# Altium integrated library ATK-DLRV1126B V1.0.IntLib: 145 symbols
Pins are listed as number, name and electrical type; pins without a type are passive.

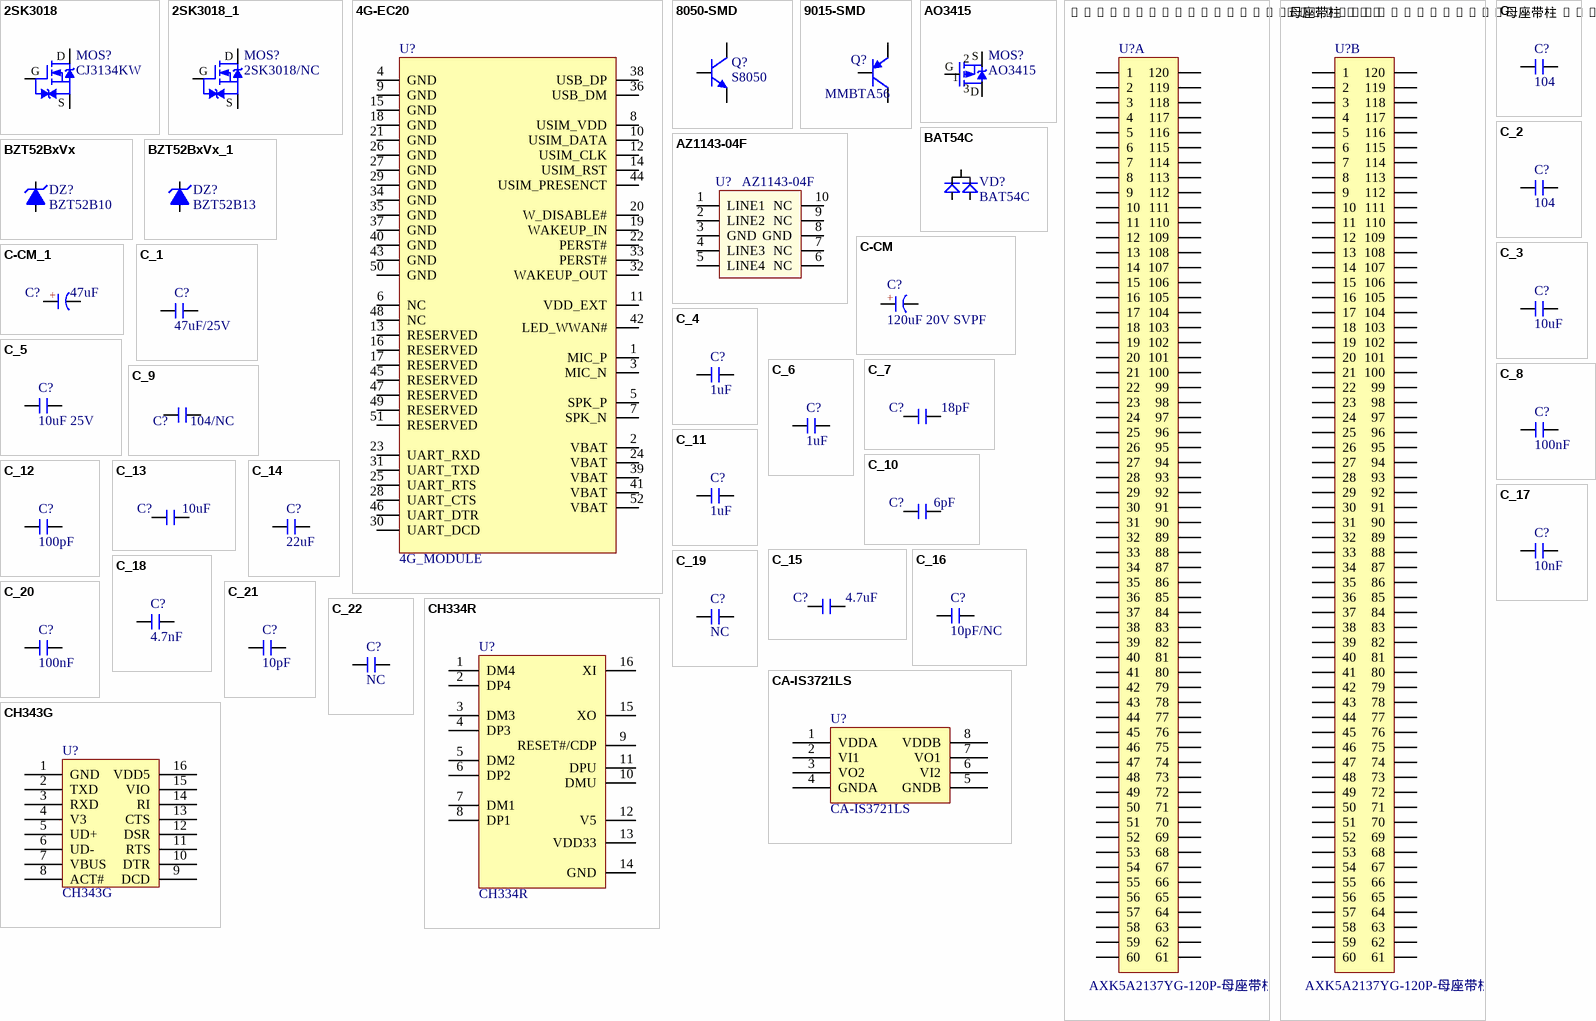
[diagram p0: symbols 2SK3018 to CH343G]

## 2SK3018
designator MOS?, comment CJ3134KW
NMOS  30V 0.1A@2.5V 8Ω; BOM名称: N沟场效应管; 版权归属: 正点原子; Parameter: MOS管
footprint SOT323-3L (2x2.2x0.9mm(长宽高))
footprint SOT323-3M (2x2.2x0.9mm(长宽高))
footprint SOT323-3N (2x2.2x0.9mm(长宽高))
footprint SOT23-3L (3x1.3x1mm(长宽高))
footprint SOT23-3N (3x1.3x1mm(长宽高))
footprint SOT23-3M (3x1.3x1mm(长宽高))
footprint SOT323-3L (2x2.2x0.9mm(长宽高))
pins: 1 G, 2 S, 3 D

## 2SK3018_1
designator MOS?, comment 2SK3018/NC
NMOS  30V 0.1A@2.5V 8Ω; BOM名称: N沟场效应管; 版权归属: 正点原子; Parameter: MOS管
footprint SOT323-3L (2x2.2x0.9mm(长宽高))
footprint SOT323-3M (2x2.2x0.9mm(长宽高))
footprint SOT323-3N (2x2.2x0.9mm(长宽高))
footprint SOT23-3L (3x1.3x1mm(长宽高))
footprint SOT23-3N (3x1.3x1mm(长宽高))
footprint SOT23-3M (3x1.3x1mm(长宽高))
footprint SOT323-3L (2x2.2x0.9mm(长宽高))
pins: 1 G, 2 S, 3 D

## 4G-EC20
designator U?, comment 4G_MODULE
footprint Mini PCIE 52P
pins: 1 MIC_P, 2 VBAT, 3 MIC_N, 4 GND, 5 SPK_P, 6 NC, 7 SPK_N, 8 USIM_VDD, 9 GND, 10 USIM_DATA, 11 VDD_EXT, 12 USIM_CLK, 13 RESERVED, 14 USIM_RST, 15 GND, 16 RESERVED, 17 RESERVED, 18 GND, 19 WAKEUP_IN, 20 W_DISABLE#, 21 GND, 22 PERST#, 23 UART_RXD, 24 VBAT, 25 UART_RTS, 26 GND, 27 GND, 28 UART_CTS, 29 GND, 30 UART_DCD, 31 UART_TXD, 32 WAKEUP_OUT, 33 PERST#, 34 GND, 35 GND, 36 USB_DM, 37 GND, 38 USB_DP, 39 VBAT, 40 GND, 41 VBAT, 42 LED_WWAN#, 43 GND, 44 USIM_PRESENCT, 45 RESERVED, 46 UART_DTR, 47 RESERVED, 48 NC, 49 RESERVED, 50 GND, 51 RESERVED, 52 VBAT

## 8050-SMD
designator Q?, comment S8050
高频放大-NPN型; 版权归属: 正点原子; 属性: 40V 1.5A 1W 100MHZ; Parameter: 三极管
footprint SOT23-3N (3x1.3x1mm(长宽高))
footprint SOT23-3L (3x1.3x1mm(长宽高))
footprint SOT23-3M (3x1.3x1mm(长宽高))
footprint SOT323-3L (2x2.2x0.9mm(长宽高))
footprint SOT323-3N (2x2.2x0.9mm(长宽高))
footprint SOT323-3M (2x2.2x0.9mm(长宽高))
pins: 1 B, 2 E, 3 C

## 9015-SMD
designator Q?, comment MMBTA56
低噪放大-PNP型; BOM名称: 三极管; 版权归属: 正点原子; 属性: 50V 0.1A 0.4W 150MHZ
footprint SOT23-3N (3x1.3x1mm(长宽高))
footprint SOT23-3L (3x1.3x1mm(长宽高))
footprint SOT23-3M (3x1.3x1mm(长宽高))
pins: 1 B, 2 E, 3 C

## AO3415
designator MOS?
PMOS -20V-4.3A 45mΩ; BOM名称: P沟道场效应管; 版权归属: 正点原子; Parameter: MOS管
footprint SOT23-3N (3x1.3x1mm(长宽高))
footprint SOT23-3L (3x1.3x1mm(长宽高))
footprint SOT23-3M (3x1.3x1mm(长宽高))
pins: 1 G, 2 S, 3 D

## AXK5A2137YG-120P-母座带柱
designator U?
footprint ATK-CLRV1126B-CORE (公座)
part A pins: A1 1, A2 2, A3 3, A4 4, A5 5, A6 6, A7 7, A8 8, A9 9, A10 10, A11 11, A12 12, A13 13, A14 14, A15 15, A16 16, A17 17, A18 18, A19 19, A20 20, A21 21, A22 22, A23 23, A24 24, A25 25, A26 26, A27 27, A28 28, A29 29, A30 30, A31 31, A32 32, A33 33, A34 34, A35 35, A36 36, A37 37, A38 38, A39 39, A40 40, A41 41, A42 42, A43 43, A44 44, A45 45, A46 46, A47 47, A48 48, A49 49, A50 50, A51 51, A52 52, A53 53, A54 54, A55 55, A56 56, A57 57, A58 58, A59 59, A60 60, A61 61, A62 62, A63 63, A64 64, A65 65, A66 66, A67 67, A68 68, A69 69, A70 70, A71 71, A72 72, A73 73, A74 74, A75 75, A76 76, A77 77, A78 78, A79 79, A80 80, A81 81, A82 82, A83 83, A84 84, A85 85, A86 86, A87 87, A88 88, A89 89, A90 90, A91 91, A92 92, A93 93, A94 94, A95 95, A96 96, A97 97, A98 98, A99 99, A100 100, A101 101, A102 102, A103 103, A104 104, A105 105, A106 106, A107 107, A108 108, A109 109, A110 110, A111 111, A112 112, A113 113, A114 114, A115 115, A116 116, A117 117, A118 118, A119 119, A120 120
part B pins: B1 1, B2 2, B3 3, B4 4, B5 5, B6 6, B7 7, B8 8, B9 9, B10 10, B11 11, B12 12, B13 13, B14 14, B15 15, B16 16, B17 17, B18 18, B19 19, B20 20, B21 21, B22 22, B23 23, B24 24, B25 25, B26 26, B27 27, B28 28, B29 29, B30 30, B31 31, B32 32, B33 33, B34 34, B35 35, B36 36, B37 37, B38 38, B39 39, B40 40, B41 41, B42 42, B43 43, B44 44, B45 45, B46 46, B47 47, B48 48, B49 49, B50 50, B51 51, B52 52, B53 53, B54 54, B55 55, B56 56, B57 57, B58 58, B59 59, B60 60, B61 61, B62 62, B63 63, B64 64, B65 65, B66 66, B67 67, B68 68, B69 69, B70 70, B71 71, B72 72, B73 73, B74 74, B75 75, B76 76, B77 77, B78 78, B79 79, B80 80, B81 81, B82 82, B83 83, B84 84, B85 85, B86 86, B87 87, B88 88, B89 89, B90 90, B91 91, B92 92, B93 93, B94 94, B95 95, B96 96, B97 97, B98 98, B99 99, B100 100, B101 101, B102 102, B103 103, B104 104, B105 105, B106 106, B107 107, B108 108, B109 109, B110 110, B111 111, B112 112, B113 113, B114 114, B115 115, B116 116, B117 117, B118 118, B119 119, B120 120

## AZ1143-04F
designator U?
ESD保护二极管阵列
footprint DFN2510P10E
pins: 1 LINE1, 2 LINE2, 3 GND, 4 LINE3, 5 LINE4, 6 NC, 7 NC, 8 GND, 9 NC, 10 NC

## BAT54C
designator VD?
肖特基二极管（双）
footprint SOT23-3N (3x1.3x1mm(长宽高))
footprint SOT23-3L (3x1.3x1mm(长宽高))
footprint SOT23-3M (3x1.3x1mm(长宽高))
pins: 1, 2, 3

## BZT52BxVx
designator DZ?, comment BZT52B10
CJ x.xV / 0.5W稳压管  2%; 版权归属: 正点原子; BOM名称: 二极管(稳压)
footprint SOD-123 (2.7x1.6X1.1mm（长宽高，不包括引脚）)
footprint SMB (二极管 SMB)
footprint SOD-123 (二极管)
pins: 1 A, 2 K

## BZT52BxVx_1
designator DZ?, comment BZT52B13
CJ x.xV / 0.5W稳压管  2%; 版权归属: 正点原子; BOM名称: 二极管(稳压)
footprint SOD-123 (2.7x1.6X1.1mm（长宽高，不包括引脚）)
footprint Model Name (Model Description)
footprint Model Name (Model Description)
footprint SMB (二极管 SMB)
footprint SOD-123 (二极管)
pins: 1 A, 2 K

## C
designator C?, comment 104
无极性贴片电容; 版权归属: 源创客
footprint C 0402 (无极性贴片电容)
pins: 1, 2

## C-CM
designator C?, comment 120uF 20V SVPF
贴片电解电容; 版权归属: 源创客
footprint CM A(3*5.4) (贴片电解电容，直径3mm，高5.4mm)
footprint CM B(4*5.4) (贴片电解电容，直径4mm，高5.4mm)
footprint CM C(5*5.4) (贴片电解电容，直径5mm，高5.4mm)
footprint CM D(6.3*5.4) (贴片电解电容，直径6.3mm，高5.4mm)
footprint CM D(6.3*7.7) (贴片电解电容，直径6.3mm，高7.7mm)
footprint CM E(8*6.2) (贴片电解电容，直径8mm，高6.2mm)
footprint CM E(8*10.2) (贴片电解电容，直径8mm，高10.2mm)
footprint CM F(10*10.2) (贴片电解电容，直径10mm，高10.2mm)
footprint CM G(12.5*13.5) (贴片电解电容，直径12.5mm，高13.5mm)
footprint CM G(12.5*16) (贴片电解电容，直径12.5mm，高16mm)
footprint CM H(16*16.5) (贴片电解电容，直径16mm，高16.5mm)
pins: 1 A, 2 K

## C-CM_1
designator C?, comment 47uF
贴片电解电容; 版权归属: 源创客
footprint CM A(3*5.4) (贴片电解电容，直径3mm，高5.4mm)
footprint CM B(4*5.4) (贴片电解电容，直径4mm，高5.4mm)
footprint CM C(5*5.4) (贴片电解电容，直径5mm，高5.4mm)
footprint CM D(6.3*5.4) (贴片电解电容，直径6.3mm，高5.4mm)
footprint CM D(6.3*7.7) (贴片电解电容，直径6.3mm，高7.7mm)
footprint CM E(8*6.2) (贴片电解电容，直径8mm，高6.2mm)
footprint CM E(8*10.2) (贴片电解电容，直径8mm，高10.2mm)
footprint CM F(10*10.2) (贴片电解电容，直径10mm，高10.2mm)
footprint CM G(12.5*13.5) (贴片电解电容，直径12.5mm，高13.5mm)
footprint CM G(12.5*16) (贴片电解电容，直径12.5mm，高16mm)
footprint CM H(16*16.5) (贴片电解电容，直径16mm，高16.5mm)
pins: 1 A, 2 K

## C_1
designator C?, comment 47uF/25V
无极性贴片电容; 版权归属: 源创客
footprint C 0201 (无极性贴片电容)
footprint C 0402 (无极性贴片电容)
footprint C 0603 (无极性贴片电容)
footprint C 0805 (无极性贴片电容)
footprint C 1206 (无极性贴片电容)
footprint C 1210 (无极性贴片电容)
footprint C 1808 (无极性贴片电容)
footprint C 1812 (无极性贴片电容)
footprint C 1825 (无极性贴片电容)
footprint C 2225 (无极性贴片电容)
pins: 1, 2

## C_2
designator C?, comment 104
无极性贴片电容; 版权归属: 源创客
footprint C 0402 (无极性贴片电容)
pins: 1, 2

## C_3
designator C?, comment 10uF
无极性贴片电容; 版权归属: 源创客
footprint C 0201 (无极性贴片电容)
footprint C 0402 (无极性贴片电容)
footprint C 0603 (无极性贴片电容)
footprint C 0805 (无极性贴片电容)
footprint C 1206 (无极性贴片电容)
footprint C 1210 (无极性贴片电容)
footprint C 1808 (无极性贴片电容)
footprint C 1812 (无极性贴片电容)
footprint C 1825 (无极性贴片电容)
footprint C 2225 (无极性贴片电容)
footprint C 0603 (无极性贴片电容(0603))
pins: 1, 2

## C_4
designator C?, comment 1uF
50V 10% 无极性贴片电容; BOM名称: 电容; 版权归属: 正点原子
footprint C 0201 (无极性贴片电容)
footprint C 0402 (无极性贴片电容)
footprint C 0603 (无极性贴片电容)
footprint C 0805 (无极性贴片电容)
footprint C 1206 (无极性贴片电容)
footprint C 1210 (无极性贴片电容)
footprint C 1808 (无极性贴片电容)
footprint C 1812 (无极性贴片电容)
footprint C 1825 (无极性贴片电容)
footprint C 2225 (无极性贴片电容)
footprint C 0805 (无极性贴片电容(0805))
footprint C 0603 (无极性贴片电容(0603))
pins: 1, 2

## C_5
designator C?, comment 10uF 25V
无极性贴片电容; 版权归属: 源创客
footprint C 0201 (无极性贴片电容)
footprint C 0402 (无极性贴片电容)
footprint C 0603 (无极性贴片电容)
footprint C 0805 (无极性贴片电容)
footprint C 1206 (无极性贴片电容)
footprint C 1210 (无极性贴片电容)
footprint C 1808 (无极性贴片电容)
footprint C 1812 (无极性贴片电容)
footprint C 1825 (无极性贴片电容)
footprint C 2225 (无极性贴片电容)
pins: 1, 2

## C_6
designator C?, comment 1uF
无极性贴片电容; 版权归属: 源创客
footprint C 0402 (无极性贴片电容)
pins: 1, 2

## C_7
designator C?, comment 18pF
无极性贴片电容; 版权归属: 源创客
footprint C 0402 (无极性贴片电容)
pins: 1, 2

## C_8
designator C?, comment 100nF
无极性电容; BOM名称: 无极性贴片电容; 版权归属: 正点原子
footprint C 0402 (无极性贴片电容(0402))
pins: 1, 2

## C_9
designator C?, comment 104/NC
无极性贴片电容; 版权归属: 正点原子
footprint C 0402 (无极性贴片电容)
pins: 1, 2

## C_10
designator C?, comment 6pF
无极性贴片电容; 版权归属: 正点原子
footprint C 0402 (无极性贴片电容)
pins: 1, 2

## C_11
designator C?, comment 1uF
无极性贴片电容; 版权归属: 正点原子
footprint C 0402 (无极性贴片电容)
pins: 1, 2

## C_12
designator C?, comment 100pF
无极性贴片电容; 版权归属: 正点原子
footprint C 0402 (无极性贴片电容)
pins: 1, 2

## C_13
designator C?, comment 10uF
无极性贴片电容; 版权归属: 正点原子
footprint C 0201 (无极性贴片电容)
footprint C 0402 (无极性贴片电容)
footprint C 0603 (无极性贴片电容)
footprint C 0805 (无极性贴片电容)
footprint C 1206 (无极性贴片电容)
footprint C 1210 (无极性贴片电容)
footprint C 1808 (无极性贴片电容)
footprint C 1812 (无极性贴片电容)
footprint C 1825 (无极性贴片电容)
footprint C 2225 (无极性贴片电容)
pins: 1, 2

## C_14
designator C?, comment 22uF
无极性贴片电容; 版权归属: 正点原子
footprint C 0201 (无极性贴片电容)
footprint C 0402 (无极性贴片电容)
footprint C 0603 (无极性贴片电容)
footprint C 0805 (无极性贴片电容)
footprint C 1206 (无极性贴片电容)
footprint C 1210 (无极性贴片电容)
footprint C 1808 (无极性贴片电容)
footprint C 1812 (无极性贴片电容)
footprint C 1825 (无极性贴片电容)
footprint C 2225 (无极性贴片电容)
pins: 1, 2

## C_15
designator C?, comment 4.7uF
无极性贴片电容; 版权归属: 正点原子
footprint C 0402 (无极性贴片电容)
pins: 1, 2

## C_16
designator C?, comment 10pF/NC
无极性贴片电容; 版权归属: 正点原子
footprint C 0402 (无极性贴片电容)
pins: 1, 2

## C_17
designator C?, comment 10nF
无极性贴片电容; 版权归属: 正点原子
footprint C 0402 (无极性贴片电容)
pins: 1, 2

## C_18
designator C?, comment 4.7nF
无极性贴片电容; 版权归属: 正点原子
footprint C 0402 (无极性贴片电容)
pins: 1, 2

## C_19
designator C?, comment NC
无极性贴片电容; 版权归属: 正点原子
footprint C 0402 (无极性贴片电容)
pins: 1, 2

## C_20
designator C?, comment 100nF
无极性贴片电容; 版权归属: 源创客
footprint C 0402 (无极性贴片电容(0402))
pins: 1, 2

## C_21
designator C?, comment 10pF
无极性贴片电容; 版权归属: 源创客
footprint C 0402 (无极性贴片电容)
pins: 1, 2

## C_22
designator C?, comment NC
无极性贴片电容; 版权归属: 源创客
footprint C 0201 (无极性贴片电容)
footprint C 0402 (无极性贴片电容)
footprint C 0603 (无极性贴片电容)
footprint C 0805 (无极性贴片电容)
footprint C 1206 (无极性贴片电容)
footprint C 1210 (无极性贴片电容)
footprint C 1808 (无极性贴片电容)
footprint C 1812 (无极性贴片电容)
footprint C 1825 (无极性贴片电容)
footprint C 2225 (无极性贴片电容)
pins: 1, 2

## CA-IS3721LS
designator U?
footprint SOIC-8 6.2*5.1 (SOIC-8 6.2*5.1mm)
pins: 1 VDDA, 2 VI1, 3 VO2, 4 GNDA, 5 GNDB, 6 VI2, 7 VO1, 8 VDDB

## CH334R
designator U?
footprint QSOP16 (TSOP, 16-Leads, Body 4.90x3.90mm, Pitch 0.64mm, IPC Low Density)
pins: 1 DM4, 2 DP4, 3 DM3, 4 DP3, 5 DM2, 6 DP2, 7 DM1, 8 DP1, 9 RESET#/CDP, 10 DMU, 11 DPU, 12 V5, 13 VDD33, 14 GND, 15 XO, 16 XI

## CH343G
designator U?
footprint SOP16_M (10.3*6.2*1.8mm（长宽高）)
pins: 1 GND, 2 TXD, 3 RXD, 4 V3, 5 UD+, 6 UD-, 7 VBUS, 8 ACT#, 9 DCD, 10 DTR, 11 RTS, 12 DSR, 13 CTS, 14 RI, 15 VIO, 16 VDD5

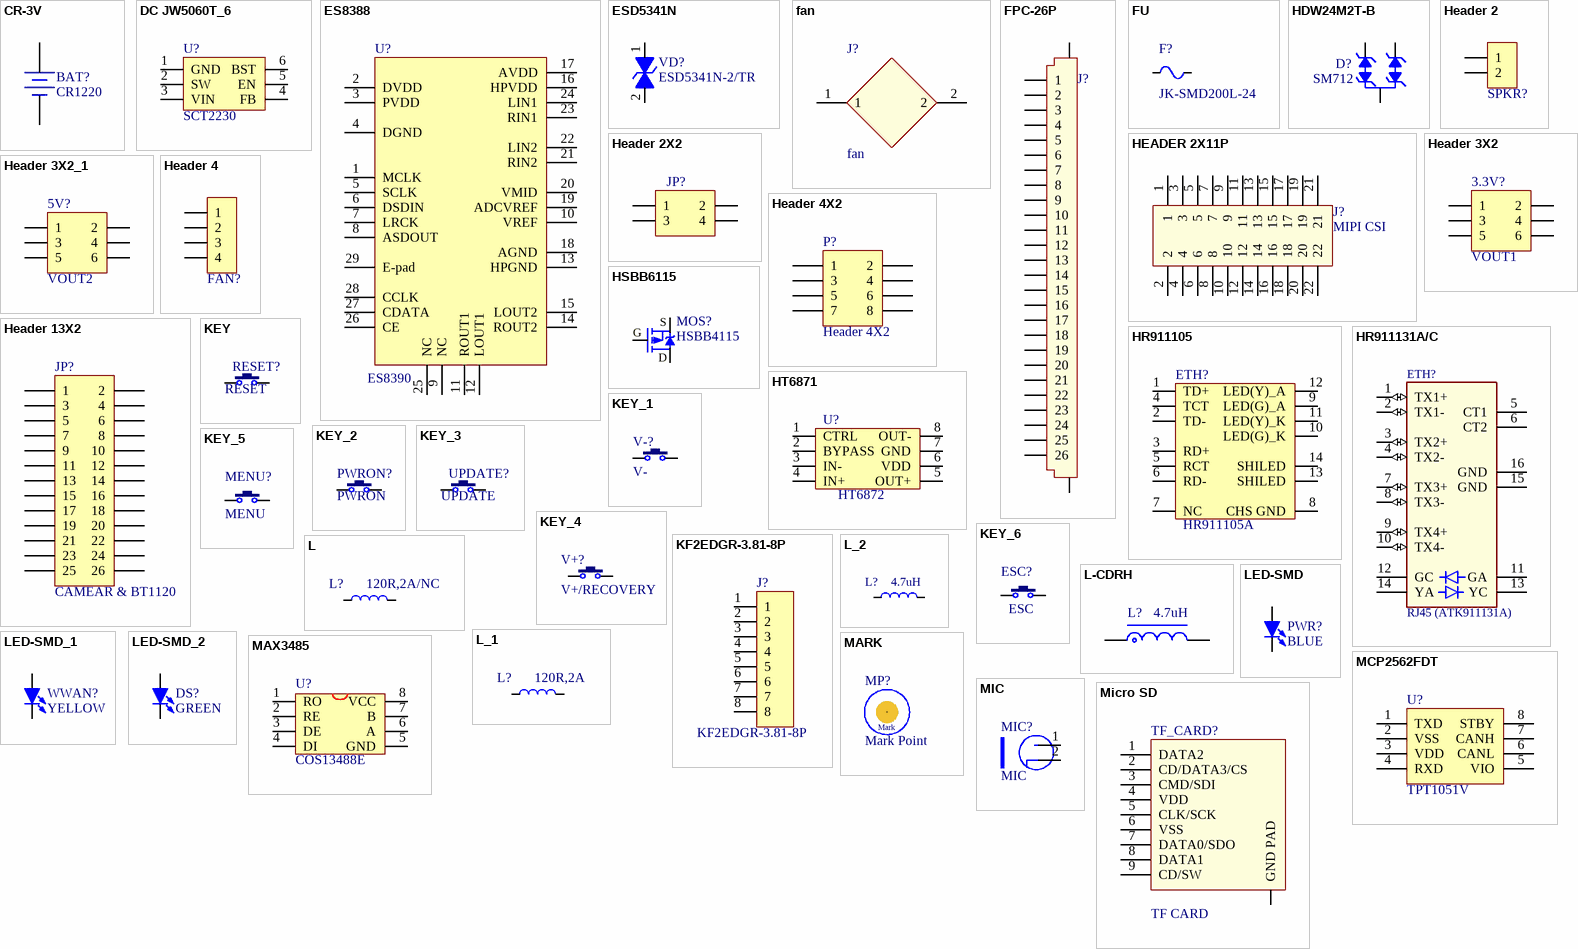
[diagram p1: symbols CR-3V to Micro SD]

## CR-3V
designator BAT?, comment CR1220
微型电池; 版权归属: 正点原子
footprint CR1220_A (纽扣电池座)
footprint CR1220_B (纽扣电池座)
footprint ML621FE (可充电纽扣电池)
footprint CR2032_A (纽扣电池座)
footprint CR2032_B (纽扣电池座)
pins: 1 DC+, 2 DC-

## DC JW5060T_6
designator U?, comment SCT2230
DC降压芯片
footprint SOT23-6L (3x1.6x1.1mm(长宽高))
footprint SOT23-6M (3x1.6x1.1mm(长宽高))
footprint SOT23-6N (3x1.6x1.1mm(长宽高))
pins: 1 GND, 2 SW, 3 VIN, 4 FB, 5 EN, 6 BST

## ES8388
designator U?, comment ES8390
footprint QFN28 4X4_L (QFN28P 长4mm，宽4mm)
pins: 1 MCLK, 2 DVDD, 3 PVDD, 4 DGND, 5 SCLK, 6 DSDIN, 7 LRCK, 8 ASDOUT, 9 NC, 10 VREF, 11 ROUT1, 12 LOUT1, 13 HPGND, 14 ROUT2, 15 LOUT2, 16 HPVDD, 17 AVDD, 18 AGND, 19 ADCVREF, 20 VMID, 21 RIN2, 22 LIN2, 23 RIN1, 24 LIN1, 25 NC, 26 CE, 27 CDATA, 28 CCLK, 29 E-pad

## ESD5341N
designator VD?, comment ESD5341N-2/TR
ESD二极管-单向
footprint ESD0402
pins: 1, 2

## fan
designator J?
footprint 40*40mm fan
footprint 40X40MM_FAN_59MM
pins: 1, 2

## FPC-26P
designator J?, comment FPC0.5-26P  (value not drawn)
FPC连接器; 版权归属: 正点原子; Parameter: 接口器件
footprint FPC 1.25 26P V-T (FPC插座1.25mm 26P 立式直插)
footprint FPC 1.0 26P H-S (FPC座1.0mm 26P 卧式贴片)
footprint FPC 0.5 26P H-S (FPC座 0.5mm 26P 卧式贴片)
footprint FPC 0.5 26P V-S (FPC座 0.5mm 26P 立式贴片)
footprint HEADER 2.0 2X11P (2.0mm 直插排针)
footprint FPC 0.5 26P V-S (FPC座 0.5mm 26P 立式贴片)
pins: 0, 0, 1, 2, 3, 4, 5, 6, 7, 8, 9, 10, 11, 12, 13, 14, 15, 16, 17, 18, 19, 20, 21, 22, 23, 24, 25, 26

## FU
designator F?, comment JK-SMD200L-24
贴片保险丝; 版权归属: 源创客
footprint FU 0402 (贴片保险丝)
footprint FU 0603 (贴片保险丝)
footprint FU 0805 (贴片保险丝)
footprint FU 1206 (贴片保险丝)
footprint FU 1210 (贴片保险丝)
footprint FU 1812 (贴片保险丝)
footprint FU 1812 (贴片保险丝)
pins: 1, 2

## HDW24M2T-B
designator D?, comment SM712
ESD
footprint SOT23-3L (3x1.3x1mm(长宽高))
pins: 1, 2, 3

## Header 2
designator SPKR?, comment SPKL  (value not drawn)
2P接插件; 版权归属: 源创客
footprint HDR-1X2 (排针，2脚)
footprint HDR-1X2_H (弯脚排针，2脚)
footprint HDR-1X2_M (排母，2脚)
footprint HDR-1X2_Y (圆孔排母，2脚)
footprint XH2.54-2P (接插件，2P)
footprint KF2510-2P (接插件/2A)
footprint VH3.96-2P (接插件，25V/5A)
footprint XH2.54-2P_H (接插件，2P)
footprint VH3.96-2P_H (接插件，25V/5A)
footprint KF301-2P (可拼接端子/6A)
footprint KF2EDGK5.0-2P (直列插拔式端子)
footprint PH2.0 D-L-2P (接插件/1A)
footprint PH2.0 D-W-2P (接插件/1A)
footprint KF2EDGK5.0-2P_H (弯角插拔式端子)
footprint KF7620-2P (15.2*12*12mm(长宽高))
footprint KF350-2P (可拼接端子/10A)
footprint KF128-3.81-2P (螺钉式接线端子，脚距3.81mm)
footprint KF128-5.08-2P (螺钉式接线端子，脚距5.08mm)
footprint PH2.0 S-W-2P (长：8mm，宽：7.6mm，高：5.5mm)
footprint KF2EDGK5.08-2P (直列插拔式端子)
footprint KF2EDGK5.08-2P_H (弯角插拔式端子)
footprint HDR2.54 S-W-2P (2P卧式贴片排针2.54)
footprint HDR2.54 S-W-2P_M (2P卧式贴片排母2.54)
footprint HDR2.0 -1X2
pins: 1, 2

## Header 2X2
designator JP?, comment Header2X2  (value not drawn)
2*2P接插件; 版权归属: 源创客
footprint HDR-2X2 (双排排针，2x2脚)
footprint HDR-2X2_H (双排弯脚排针，2x2脚)
footprint PHB2.0-2x2 (长：6mm，宽：7.3mm，高：7.8mm)
footprint PHD2.0-2x2P (4脚，长：6mm，宽：5mm，高：6.5mm)
footprint HDR2.54 2x2-M-SMD (脚距：2.54mm，贴片双排母)
pins: 1, 2, 3, 4

## HEADER 2X11P
designator J?, comment MIPI CSI
footprint HEADER 2.0 2X11P (2.0mm 直插排针)
pins: 1, 2, 3, 4, 5, 6, 7, 8, 9, 10, 11, 12, 13, 14, 15, 16, 17, 18, 19, 20, 21, 22

## Header 3X2
designator 3.3V?, comment VOUT1
3*2P接插件; 版权归属: 源创客
footprint HDR-3X2 (双排弯脚排针，3x2脚)
footprint IDC2.54-6P (6P简易牛角座)
footprint HDR-3X2_H (双排弯脚排针，3x2脚)
footprint PHB2.0-2x3 (长：8mm，宽：7.3mm，高：7.8mm)
footprint PHD2.0-2x3P (6脚，长：8mm，宽：5mm，高：6.5mm)
footprint HDR2.54 2x3-M-SMD (脚距：2.54mm，贴片双排母)
pins: 1, 2, 3, 4, 5, 6

## Header 3X2_1
designator 5V?, comment VOUT2
3*2P接插件; 版权归属: 源创客
footprint HDR-3X2 (双排弯脚排针，3x2脚)
footprint IDC2.54-6P (6P简易牛角座)
footprint HDR-3X2_H (双排弯脚排针，3x2脚)
footprint PHB2.0-2x3 (长：8mm，宽：7.3mm，高：7.8mm)
footprint PHD2.0-2x3P (6脚，长：8mm，宽：5mm，高：6.5mm)
footprint HDR2.54 2x3-M-SMD (脚距：2.54mm，贴片双排母)
pins: 1, 2, 3, 4, 5, 6

## Header 4
designator FAN?, comment HDR-1X4  (value not drawn)
4P接插件; 版权归属: 正点原子; Parameter: 接插件
footprint HDR-1X4 (排针，4脚)
footprint HDR-1X4_M (排母，4脚)
footprint XH2.54-4P (接插件，4P)
footprint KF2510-4P (接插件/2A)
footprint VH3.96-4P_H (接插件，25V/5A)
footprint PH2.0 D-L-4P (接插件/1A)
footprint HDR-1X4_H (弯脚排针，4脚)
footprint HDR-1X4_Y (圆孔排母，4脚)
footprint XH2.54-4P_H (接插件，4P)
footprint PH2.0 D-W-4P (接插件/1A)
footprint KF301-4P (可拼接端子/6A)
footprint KF2EDGK5.0-4P (直列插拔式端子)
footprint KF2EDGK5.0-4P_H (弯角插拔式端子)
footprint KF7620-4P (30.5*12*12mm(长宽高))
footprint KF350-4P (可拼接端子/10A)
footprint KF128-3.81-4P (螺钉式接线端子，脚距3.81mm)
footprint KF128-5.08-4P (螺钉式接线端子，脚距5.08mm)
footprint VH3.96-4P (接插件，25V/5A)
footprint PH2.0 S-W-4P (长：12mm，宽：7.6mm，高：5.5mm)
footprint KF2EDGK5.08-4P (直列插拔式端子)
footprint KF2EDGK5.08-4P_H (弯角插拔式端子)
footprint HDR2.54 S-W-4P (4P卧式贴片排针2.54)
footprint HDR2.54 S-W-4P_M (4P卧式贴片排母2.54)
footprint SH1.0 S-W-4P (SH1.0MM间距卧贴连接座子)
footprint HDR2.0 -1X4
footprint HDR-1x4-1.25MM
footprint SH1.0 S-L-4P (SH1.0MM间距立式连接座子)
footprint HT3.96R-4P_H (接插件，250V/8A)
footprint PH2.0 D-L-4P (接插件/1A)
pins: 1, 2, 3, 4

## Header 4X2
designator P?
Header, 4-Pin, Dual row
footprint HDR-4X2 (双排排针，3x2脚)
signal-integrity model Connector
pins: 1, 2, 3, 4, 5, 6, 7, 8

## Header 13X2
designator JP?, comment CAMEAR & BT1120
Header, 13-Pin, Dual row
footprint Header 2.54 2X13P (排针(2X13P,2.54,直插))
signal-integrity model Connector
pins: 1, 2, 3, 4, 5, 6, 7, 8, 9, 10, 11, 12, 13, 14, 15, 16, 17, 18, 19, 20, 21, 22, 23, 24, 25, 26

## HR911105
designator ETH?, comment HR911105A
footprint HR911105A (NET_WORK)
pins: 1 TD+, 2 TD-, 3 RD+, 4 TCT, 5 RCT, 6 RD-, 7 NC, 8 CHS GND, 9 LED(G)_A, 10 LED(G)_K, 11 LED(Y)_K, 12 LED(Y)_A, 13 SHILED, 14 SHILED

## HR911131A/C
designator ETH?, comment RJ45 (ATK911131A)
千兆以太网接口
footprint HR911131C (千兆网络RJ45座子)
footprint HR911131A (千兆网络RJ45座子)
pins: 1 TX1+ (io), 2 TX1- (io), 3 TX2+ (io), 4 TX2- (io), 5 CT1, 6 CT2, 7 TX3+ (io), 8 TX3- (io), 9 TX4+ (io), 10 TX4- (io), 11 GA, 12 GC, 13 YC, 14 YA, 15 GND (power), 16 GND (power)

## HSBB6115
designator MOS?, comment HSBB4115
PMOS -60V -8A@-4.5V 33mΩ; BOM名称: MOS管; 版权归属: 正点原子
footprint DFN3.3x3.3_8L_EP1
footprint VDFN10-3X3
footprint DFN8_ 3x3
pins: 1 S, 2 S, 3 G, 4 G, 5 D, 6 D, 7 D, 8 D

## HT6871
designator U?, comment HT6872
HT6871
footprint SOP8_N (5*6*1.8mm（长宽高）)
pins: 1 CTRL, 2 BYPASS, 3 IN-, 4 IN+, 5 OUT+, 6 VDD, 7 GND, 8 OUT-

## KEY
designator RESET?, comment RESET
按键; BOM名称: 3x6轻触开关; 版权归属: 正点原子
footprint TSW DIP-6*6*5 (6*6*5mm)
footprint TSW SMD-2S
footprint TSW SMD-3*6*2.5 (3*6*2.5mm)
footprint TSW SMD-3*6*4.3 (3*6*4.3mm)
footprint TSW SMD-3*6*5 (3*6*5mm)
footprint KEY_SOP324225 (KEY,3.2mm*4.2mm*2.5mm)
pins: 1, 2

## KEY_1
designator V-?, comment V-
按键; BOM名称: 3x6轻触开关; 版权归属: 正点原子
footprint TSW DIP-6*6*5 (6*6*5mm)
footprint TSW SMD-2S
footprint TSW SMD-3*6*2.5 (3*6*2.5mm)
footprint TSW SMD-3*6*4.3 (3*6*4.3mm)
footprint TSW SMD-3*6*5 (3*6*5mm)
footprint KEY_SOP324225 (KEY,3.2mm*4.2mm*2.5mm)
pins: 1, 2

## KEY_2
designator PWRON?, comment PWRON
按键; BOM名称: 3x6轻触开关; 版权归属: 正点原子
footprint TSW DIP-6*6*5 (6*6*5mm)
footprint TSW SMD-2S
footprint TSW SMD-3*6*2.5 (3*6*2.5mm)
footprint TSW SMD-3*6*4.3 (3*6*4.3mm)
footprint TSW SMD-3*6*5 (3*6*5mm)
footprint KEY_SOP324225 (KEY,3.2mm*4.2mm*2.5mm)
pins: 1, 2

## KEY_3
designator UPDATE?, comment UPDATE
按键; BOM名称: 3x6轻触开关; 版权归属: 正点原子
footprint TSW DIP-6*6*5 (6*6*5mm)
footprint TSW SMD-2S
footprint TSW SMD-3*6*2.5 (3*6*2.5mm)
footprint TSW SMD-3*6*4.3 (3*6*4.3mm)
footprint TSW SMD-3*6*5 (3*6*5mm)
footprint KEY_SOP324225 (KEY,3.2mm*4.2mm*2.5mm)
pins: 1, 2

## KEY_4
designator V+?, comment V+/RECOVERY
按键; BOM名称: 3x6轻触开关; 版权归属: 正点原子
footprint TSW DIP-6*6*5 (6*6*5mm)
footprint TSW SMD-2S
footprint TSW SMD-3*6*2.5 (3*6*2.5mm)
footprint TSW SMD-3*6*4.3 (3*6*4.3mm)
footprint TSW SMD-3*6*5 (3*6*5mm)
footprint KEY_SOP324225 (KEY,3.2mm*4.2mm*2.5mm)
pins: 1, 2

## KEY_5
designator MENU?, comment MENU
按键; BOM名称: 3x6轻触开关; 版权归属: 正点原子
footprint TSW DIP-6*6*5 (6*6*5mm)
footprint TSW SMD-2S
footprint TSW SMD-3*6*2.5 (3*6*2.5mm)
footprint TSW SMD-3*6*4.3 (3*6*4.3mm)
footprint TSW SMD-3*6*5 (3*6*5mm)
footprint KEY_SOP324225 (KEY,3.2mm*4.2mm*2.5mm)
pins: 1, 2

## KEY_6
designator ESC?, comment ESC
按键; BOM名称: 3x6轻触开关; 版权归属: 正点原子
footprint TSW DIP-6*6*5 (6*6*5mm)
footprint TSW SMD-2S
footprint TSW SMD-3*6*2.5 (3*6*2.5mm)
footprint TSW SMD-3*6*4.3 (3*6*4.3mm)
footprint TSW SMD-3*6*5 (3*6*5mm)
footprint KEY_SOP324225 (KEY,3.2mm*4.2mm*2.5mm)
pins: 1, 2

## KF2EDGR-3.81-8P
designator J?
接线端子,8脚,间距3.81mm
footprint KF2EDGR_3.81_8P
pins: 1, 2, 3, 4, 5, 6, 7, 8

## L
designator L?, comment 120R,2A/NC
小功率贴片电感磁珠; 版权归属: 正点原子
footprint L 0402 (小功率贴片电感)
footprint L 0603 (小功率贴片电感)
footprint L 0805 (小功率贴片电感)
footprint L 1206 (小功率贴片电感)
footprint L 1210 (小功率贴片电感)
footprint L 1806 (小功率贴片电感)
footprint L 1812 (小功率贴片电感)
footprint L 1008 (2.5mm*2.0mm*1.2mm(长*宽*高）)
footprint L_2520
pins: 1, 2

## L-CDRH
designator L?, comment 4.7uH
功率屏蔽电感; 版权归属: 源创客
footprint CDRH73 (7.3*7.3*3.4mm（长宽高）)
footprint CDRH74 (7.3*7.3*4.5mm（长宽高）)
footprint CDRH124 (12*12*4.5mm（长宽高）)
footprint CDRH125 (12*12*5mm（长宽高）)
footprint CDRH127 (12*12*8mm（长宽高）)
footprint CDRH129 (12*12*9.5mm（长宽高）)
footprint L-SMD-0420 (一体化成型电感 4*4.5*2mm（长宽高）)
pins: 1, 2

## L_1
designator L?, comment 120R,2A
小功率贴片电感磁珠; 版权归属: 正点原子
footprint L 0402 (小功率贴片电感)
footprint L 0603 (小功率贴片电感)
footprint L 0805 (小功率贴片电感)
footprint L 1206 (小功率贴片电感)
footprint L 1210 (小功率贴片电感)
footprint L 1806 (小功率贴片电感)
footprint L 1812 (小功率贴片电感)
footprint L 1008 (2.5mm*2.0mm*1.2mm(长*宽*高）)
footprint L_2520
pins: 1, 2

## L_2
designator L?, comment 4.7uH
小功率贴片电感磁珠; 版权归属: 源创客
footprint L 0402 (小功率贴片电感)
footprint L 0603 (小功率贴片电感)
footprint L 0805 (小功率贴片电感)
footprint L 1206 (小功率贴片电感)
footprint L 1210 (小功率贴片电感)
footprint L 1806 (小功率贴片电感)
footprint L 1812 (小功率贴片电感)
footprint L 1008 (2.5mm*2.0mm*1.2mm(长*宽*高）)
footprint L_2520
pins: 1, 2

## LED-SMD
designator PWR?, comment BLUE
贴片LED; 版权归属: 源创客
footprint LED 0603W (白色0603LED)
footprint LED 0603R (红色0603LED)
footprint LED 0603B (蓝色0603LED)
footprint LED 0603G (绿色0603LED)
footprint LED 0603Y (黄色0603LED)
footprint LED 0805G (绿色0805LED)
footprint LED 0805R (红色0805LED)
footprint LED 0805B (蓝色0805LED)
footprint LED 0805Y (黄色0805LED)
footprint LED 3528 (白色3528LED)
footprint LED 1206G (绿色1206LED)
footprint LED 5730-V (紫色5730LED)
footprint LED 1206Y (黄色1206LED)
footprint LED 0805W (白色0805LED)
footprint LED 1206B (蓝色1206LED)
footprint LED 1206W (白色1206LED)
footprint LED 1206R (红色1206LED)
pins: 1 A, 2 K

## LED-SMD_1
designator WWAN?, comment YELLOW
贴片LED; 版权归属: 正点原子
footprint LED 0603W (白色0603LED)
footprint LED 0603R (红色0603LED)
footprint LED 0603B (蓝色0603LED)
footprint LED 0603G (绿色0603LED)
footprint LED 0603Y (黄色0603LED)
footprint LED 0805G (绿色0805LED)
footprint LED 0805R (红色0805LED)
footprint LED 0805B (蓝色0805LED)
footprint LED 0805Y (黄色0805LED)
footprint LED 3528 (白色3528LED)
footprint LED 1206G (绿色1206LED)
footprint LED 5730-V (紫色5730LED)
footprint LED 1206Y (黄色1206LED)
footprint LED 0805W (白色0805LED)
footprint LED 1206B (蓝色1206LED)
footprint LED 1206W (白色1206LED)
footprint LED 1206R (红色1206LED)
pins: 1 A, 2 K

## LED-SMD_2
designator DS?, comment GREEN
贴片LED; 版权归属: 正点原子; Parameter: 发光二极管
footprint LED 0603W (白色0603LED)
footprint LED 0603R (红色0603LED)
footprint LED 0603B (蓝色0603LED)
footprint LED 0603G (绿色0603LED)
footprint LED 0603Y (黄色0603LED)
footprint LED 0805G (绿色0805LED)
footprint LED 0805R (红色0805LED)
footprint LED 0805B (蓝色0805LED)
footprint LED 0805Y (黄色0805LED)
footprint LED 3528 (白色3528LED)
footprint LED 1206G (绿色1206LED)
footprint LED 5730-V (紫色5730LED)
footprint LED 1206Y (黄色1206LED)
footprint LED 0805W (白色0805LED)
footprint LED 1206B (蓝色1206LED)
footprint LED 1206W (白色1206LED)
footprint LED 1206R (红色1206LED)
pins: 1 A, 2 K

## MARK
designator MP?, comment Mark Point
footprint MTG_HOLE_M3 (M3l螺丝孔)
footprint MARK POINT (Footprint not found)
pins: 1

## MAX3485
designator U?, comment COS13488E
footprint SOP8_L (5*6*1.8mm（长宽高）)
footprint SOP8_N
pins: 1 RO, 2 RE, 3 DE, 4 DI, 5 GND, 6 A, 7 B, 8 VCC

## MCP2562FDT
designator U?, comment TPT1051V
footprint SOP8_N (5*6*1.8mm（长宽高）)
pins: 1 TXD, 2 VSS, 3 VDD, 4 RXD, 5 VIO, 6 CANL, 7 CANH, 8 STBY

## MIC
designator MIC?
footprint MIC-6022 (6mm*2.2mm)
footprint MIC-9767 (9.7mm*6.7mm)
pins: 1 VCC, 2 GND
1 alternate drawing of the same symbol

## Micro SD
designator TF_CARD?, comment TF CARD
Micro SD卡; 版权归属: 正点原子
footprint Micro SD
pins: 0 GND PAD, 1 DATA2, 2 CD/DATA3/CS, 3 CMD/SDI, 4 VDD, 5 CLK/SCK, 6 VSS, 7 DATA0/SDO, 8 DATA1, 9 CD/SW

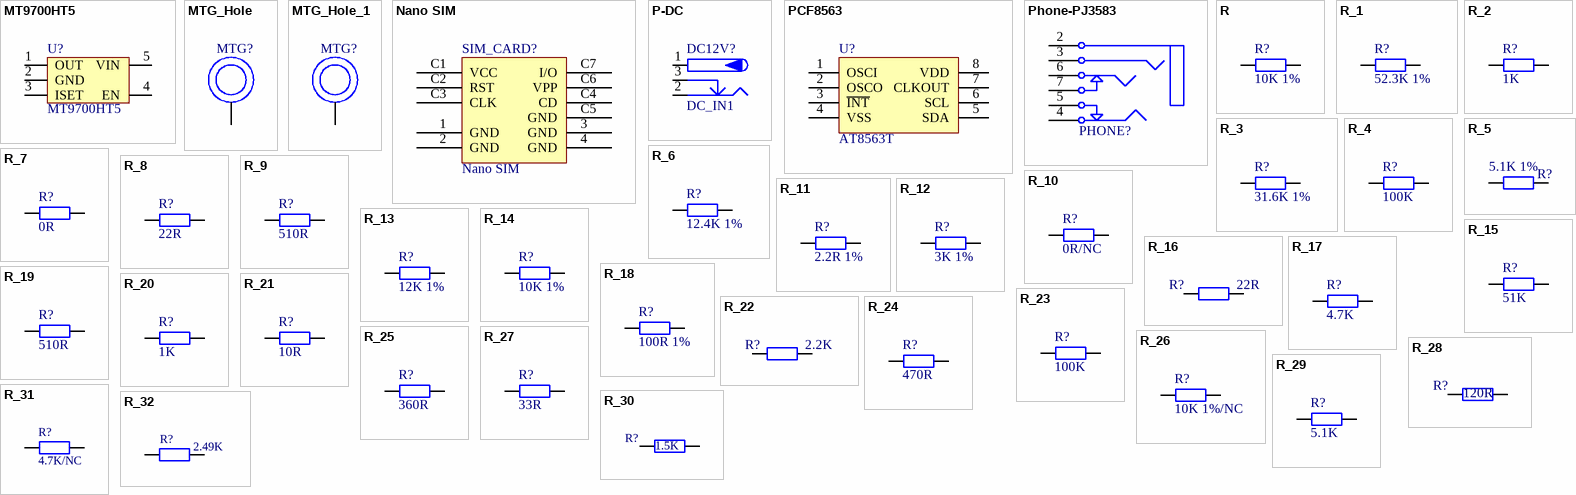
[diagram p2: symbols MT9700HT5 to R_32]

## MT9700HT5
designator U?
功率开关(5.5V-2A); BOM名称: 稳压芯片; 版权归属: 正点原子
footprint SOT23-5L (3x1.6x1.1mm(长宽高))
footprint SOT23-5N (3x1.6x1.1mm(长宽高))
footprint SOT23-5M (3x1.6x1.1mm(长宽高))
pins: 1 OUT, 2 GND, 3 ISET, 4 EN, 5 VIN

## MTG_Hole
designator MTG?, comment 螺母(M2,贴片螺母柱,铜镀镍,M2x4x1.5+2.9x1.0)  (value not drawn)
301020006
footprint MTG_HOLE_M3 (M3l螺丝孔)
footprint M2螺丝贴片螺母-直径4mm-高1.5mm (M3l螺丝孔)
pins: 1

## MTG_Hole_1
designator MTG?, comment 螺母(M3*6,贴片螺母柱,白色,SMTSO-M3-6ET)  (value not drawn)
301020001
footprint MTG_HOLE_M3 (M3l螺丝孔)
footprint M3*23+6
pins: 1

## Nano SIM
designator SIM_CARD?
footprint Nano SIM 7P
pins: 1 GND, 2 GND, 3 GND, 4 GND, C1 VCC, C2 RST, C3 CLK, C4 NC hidden, C4 CD, C5 GND, C6 VPP, C7 I/O

## P-DC
designator DC12V?, comment DC_IN1
低压电源接口; BOM名称: DC电源接口; 版权归属: 源创客
footprint DC-012 (5.5*2.1)
footprint DC-005 (5.5*2.1mm，DC30V,2.5A)
footprint DC-002 (3.5*1.1mm,)
footprint DC-003 (3.5*1.1mm)
footprint DC-003A (3.5*1.1mm)
footprint DC-050 (5.5*2.1)
footprint DC10B
pins: 1 (power), 2 (power), 3 (power)

## PCF8563
designator U?, comment AT8563T
footprint TSSOP8 (TSOP, 8-Leads, Body 3.00x3.00mm, Pitch 0.65mm, IPC Medium Density)
footprint SOP8_N (5*6*1.8mm（长宽高）)
pins: 1 OSCI, 2 OSCO, 3 ~{INT}, 4 VSS, 5 SDA, 6 SCL, 7 CLKOUT, 8 VDD

## Phone-PJ3583
designator PHONE?, comment PJ342  (value not drawn)
3.5耳机插座,带检测和麦克风; BOM名称: 耳机插座; 版权归属: 正点原子; Parameter: 接口器件
footprint pj-342b-tx-smt
footprint PJ342A
pins: 2, 3, 4, 5, 6, 7

## R
designator R?, comment 10K 1%
贴片电阻; 版权归属: 源创客
footprint R 0402 (1/16W贴片电阻)
pins: 1, 2

## R_1
designator R?, comment 52.3K 1%
贴片电阻; 版权归属: 源创客
footprint R 0402 (1/16W贴片电阻)
pins: 1, 2

## R_2
designator R?, comment 1K
贴片电阻; 版权归属: 源创客
footprint R 0402 (1/16W贴片电阻)
pins: 1, 2

## R_3
designator R?, comment 31.6K 1%
贴片电阻; 版权归属: 源创客
footprint R 0402 (1/16W贴片电阻)
pins: 1, 2

## R_4
designator R?, comment 100K
贴片电阻; 版权归属: 源创客
footprint R 0402 (1/16W贴片电阻)
pins: 1, 2

## R_5
designator R?, comment 5.1K 1%
贴片电阻; 版权归属: 源创客
footprint R 0402 (1/16W贴片电阻)
pins: 1, 2

## R_6
designator R?, comment 12.4K 1%
贴片电阻; 版权归属: 源创客
footprint R 0402 (1/16W贴片电阻)
pins: 1, 2

## R_7
designator R?, comment 0R
贴片电阻; 版权归属: 正点原子
footprint R 0402 (1/16W贴片电阻)
pins: 1, 2

## R_8
designator R?, comment 22R
贴片电阻; BOM名称: 电阻; 版权归属: 正点原子
footprint R 0402 (1/16W贴片电阻)
footprint R 0603 (1/10W贴片电阻)
pins: 1, 2

## R_9
designator R?, comment 510R
贴片电阻; BOM名称: 电阻; 版权归属: 正点原子
footprint R 0402 (1/16W贴片电阻)
footprint R 0603 (1/10W贴片电阻)
pins: 1, 2

## R_10
designator R?, comment 0R/NC
贴片电阻; BOM名称: 电阻; 版权归属: 正点原子
footprint R 0402 (1/16W贴片电阻)
footprint R 0603 (1/10W贴片电阻)
pins: 1, 2

## R_11
designator R?, comment 2.2R 1%
贴片电阻; 版权归属: 源创客
footprint R 0402 (1/16W贴片电阻)
pins: 1, 2

## R_12
designator R?, comment 3K 1%
贴片电阻; 版权归属: 正点原子
footprint R 0402 (1/16W贴片电阻)
pins: 1, 2

## R_13
designator R?, comment 12K 1%
贴片电阻; 版权归属: 正点原子
footprint R 0402 (1/16W贴片电阻)
pins: 1, 2

## R_14
designator R?, comment 10K 1%
贴片电阻; 版权归属: 正点原子
footprint R 0402 (1/16W贴片电阻)
pins: 1, 2

## R_15
designator R?, comment 51K
贴片电阻; 版权归属: 正点原子
footprint R 0402 (1/16W贴片电阻)
pins: 1, 2

## R_16
designator R?, comment 22R
贴片电阻; 版权归属: 正点原子
footprint R 0402 (1/16W贴片电阻)
pins: 1, 2

## R_17
designator R?, comment 4.7K
贴片电阻; 版权归属: 正点原子
footprint R 0402 (1/16W贴片电阻)
pins: 1, 2

## R_18
designator R?, comment 100R 1%
贴片电阻; 版权归属: 正点原子
footprint R 0402 (1/16W贴片电阻)
pins: 1, 2

## R_19
designator R?, comment 510R
贴片电阻; 版权归属: 正点原子
footprint R 0402 (1/16W贴片电阻)
pins: 1, 2

## R_20
designator R?, comment 1K
贴片电阻; 版权归属: 正点原子
footprint R 0402 (1/16W贴片电阻)
pins: 1, 2

## R_21
designator R?, comment 10R
贴片电阻; 版权归属: 正点原子
footprint R 0402 (1/16W贴片电阻)
pins: 1, 2

## R_22
designator R?, comment 2.2K
贴片电阻; 版权归属: 正点原子
footprint R 0402 (1/16W贴片电阻)
pins: 1, 2

## R_23
designator R?, comment 100K
贴片电阻; 版权归属: 正点原子
footprint R 0402 (1/16W贴片电阻)
pins: 1, 2

## R_24
designator R?, comment 470R
贴片电阻; 版权归属: 正点原子
footprint R 0402 (1/16W贴片电阻)
pins: 1, 2

## R_25
designator R?, comment 360R
贴片电阻; 版权归属: 正点原子
footprint R 0201 (1/20W贴片电阻)
footprint R 0201-HP (1/20W高精度贴片电阻)
footprint R 0402 (1/16W贴片电阻)
footprint R 0402-HP (1/16W高精度贴片电阻)
footprint R 0603 (1/10W贴片电阻)
footprint R 0603-HP (1/10W高精度贴片电阻)
footprint R 0805 (1/8W贴片电阻)
footprint R 0805-HP (1/8W高精度贴片电阻)
footprint R 1206 (1/4W贴片电阻)
footprint R 1206-HP (1/4W高精度贴片电阻)
footprint R 1210 (1/3W贴片电阻)
footprint R 1210-HP (1/3W高精度贴片电阻)
footprint R 1812 (1/2W贴片电阻)
footprint R 1812-HP (1/2W高精度贴片电阻)
footprint R 2010 (3/4W贴片电阻)
footprint R 2010-HP (3/4W高精度贴片电阻)
footprint R 2512 (1W贴片电阻)
footprint R 2512-HP (1W高精度贴片电阻)
footprint R 2728-HP (4W高精度贴片电阻)
footprint LR 2725 (4W高精度贴片电阻)
pins: 1, 2

## R_26
designator R?, comment 10K 1%/NC
贴片电阻; 版权归属: 正点原子
footprint R 0402 (1/16W贴片电阻)
pins: 1, 2

## R_27
designator R?, comment 33R
贴片电阻; 版权归属: 正点原子
footprint R 0402 (1/16W贴片电阻)
pins: 1, 2

## R_28
designator R?, comment 120R
贴片电阻; 版权归属: 正点原子
footprint R 0402 (1/16W贴片电阻)
pins: 1, 2

## R_29
designator R?, comment 5.1K
贴片电阻; BOM名称: 电阻; 版权归属: 正点原子
footprint R 0402 (1/16W贴片电阻)
footprint R 0603 (1/10W贴片电阻)
pins: 1, 2

## R_30
designator R?, comment 1.5K
贴片电阻; 版权归属: 源创客
footprint R 0402 (1/16W贴片电阻)
pins: 1, 2

## R_31
designator R?, comment 4.7K/NC
贴片电阻; 版权归属: 源创客
footprint R 0402 (1/16W贴片电阻)
pins: 1, 2

## R_32
designator R?, comment 2.49K
贴片电阻; 版权归属: 源创客
footprint R 0402 (1/16W贴片电阻)
pins: 1, 2

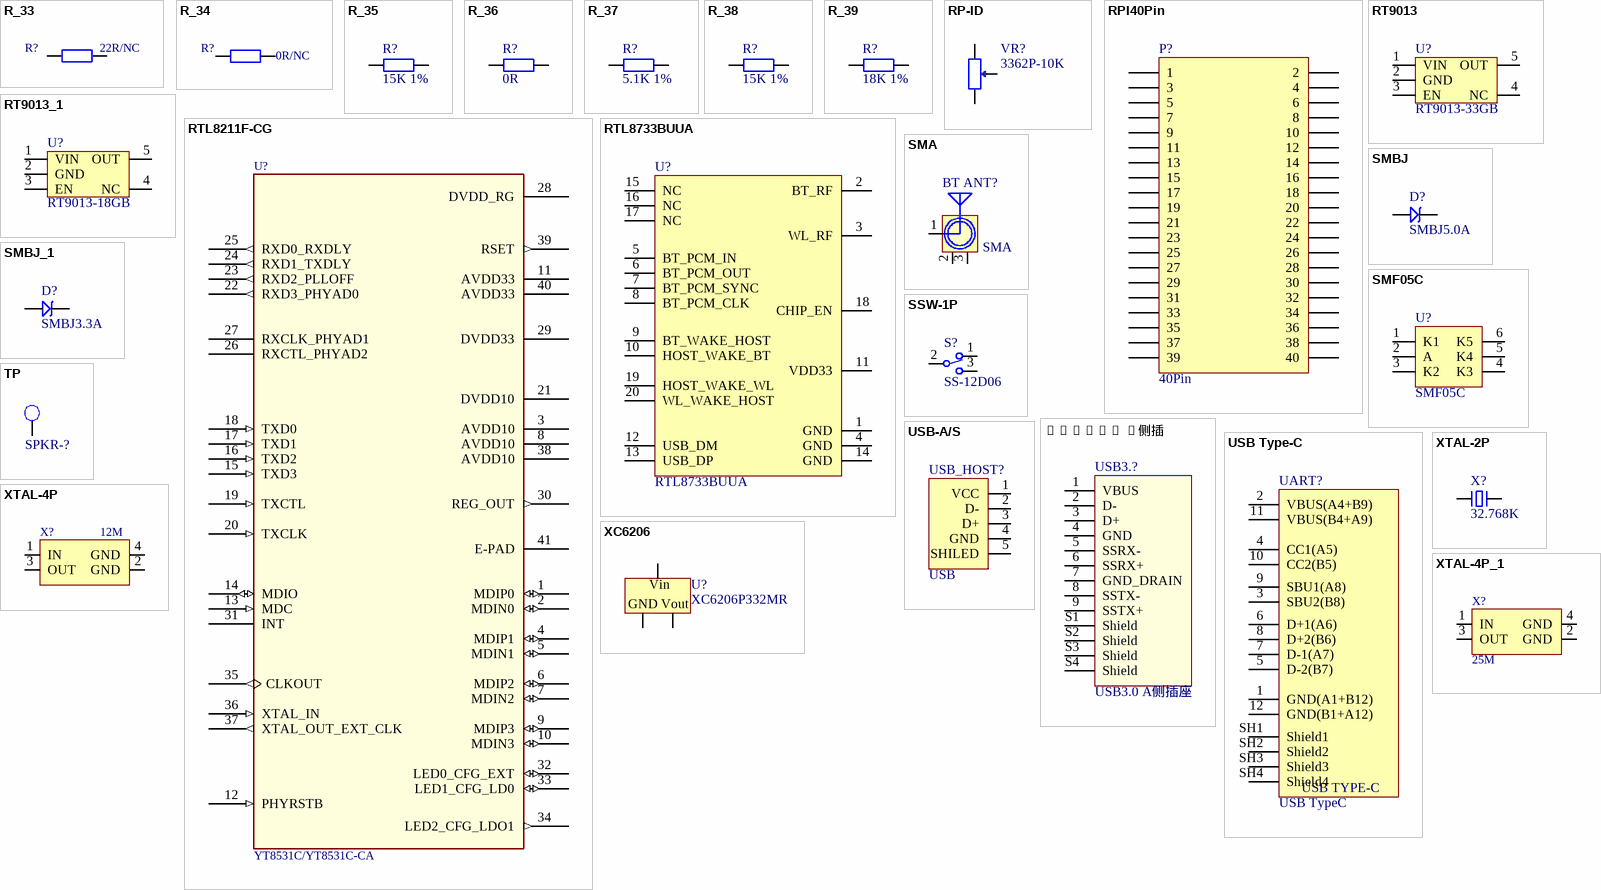
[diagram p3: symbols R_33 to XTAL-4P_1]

## R_33
designator R?, comment 22R/NC
贴片电阻; 版权归属: 源创客
footprint R 0402 (1/16W贴片电阻)
pins: 1, 2

## R_34
designator R?, comment 0R/NC
贴片电阻; 版权归属: 源创客
footprint R 0201 (1/20W贴片电阻)
footprint R 0201-HP (1/20W高精度贴片电阻)
footprint R 0402 (1/16W贴片电阻)
footprint R 0402-HP (1/16W高精度贴片电阻)
footprint R 0402 (1/16W贴片电阻)
footprint R 0603-HP (1/10W高精度贴片电阻)
footprint R 0805 (1/8W贴片电阻)
footprint R 0805-HP (1/8W高精度贴片电阻)
footprint R 1206 (1/4W贴片电阻)
footprint R 1206-HP (1/4W高精度贴片电阻)
footprint R 1210 (1/3W贴片电阻)
footprint R 1210-HP (1/3W高精度贴片电阻)
footprint R 1812 (1/2W贴片电阻)
footprint R 1812-HP (1/2W高精度贴片电阻)
footprint R 2010 (3/4W贴片电阻)
footprint R 2010-HP (3/4W高精度贴片电阻)
footprint R 2512 (1W贴片电阻)
footprint R 2512-HP (1W高精度贴片电阻)
footprint R 2728-HP (4W高精度贴片电阻)
footprint LR 2725 (4W高精度贴片电阻)
pins: 1, 2

## R_35
designator R?, comment 15K 1%
贴片电阻; BOM名称: 电阻; 版权归属: 正点原子
footprint R 0402 (1/16W贴片电阻)
footprint R 0603 (1/10W贴片电阻)
pins: 1, 2

## R_36
designator R?, comment 0R
贴片电阻; BOM名称: 电阻; 版权归属: 正点原子
footprint R 0402 (1/16W贴片电阻)
footprint R 0603 (1/10W贴片电阻)
pins: 1, 2

## R_37
designator R?, comment 5.1K 1%
贴片电阻; BOM名称: 电阻; 版权归属: 正点原子
footprint R 0402 (1/16W贴片电阻)
footprint R 0603 (1/10W贴片电阻)
pins: 1, 2

## R_38
designator R?, comment 15K 1%
贴片电阻; 版权归属: 正点原子
footprint R 0402 (1/16W贴片电阻)
pins: 1, 2

## R_39
designator R?, comment 18K 1%
贴片电阻; 版权归属: 正点原子
footprint R 0402 (1/16W贴片电阻)
pins: 1, 2

## RP-ID
designator VR?, comment 3362P-10K
插件单联电位器; BOM名称: 插件电位器; 版权归属: 正点原子
footprint 3296W (Precise Multi-Winding Adjustable Resistor)
footprint 3306W
footprint 3319P
footprint 3362P
footprint 3386W
footprint RM065 (蓝白可调电位器)
footprint WH148-1-G15 (单联电位器，脚距：5mm，柄长：15mm)
footprint WH148-1-G18 (单联电位器，脚距：5mm，柄长：18mm)
footprint WH148-1-G20 (单联电位器，脚距：5mm，柄长：20mm)
footprint WH148-1-G25 (单联电位器，脚距：5mm，柄长：25mm)
footprint 3266W (长：7mm，宽：4.8mm，高：7.5mm)
footprint 3266X (长：7mm，宽：4.8mm，高：7.5mm)
footprint 3266Y (长：7mm，宽：4.8mm，高：7.5mm)
footprint 3266Z (长：7mm，宽：4.8mm，高：7.5mm)
footprint XV09223NPV-20F (长9.85mm，宽11.55mm，高20mm)
footprint XV09223NPV-25F (长9.85mm，宽11.55mm，高25mm)
footprint XV09223NPV-30F (长9.85mm，宽11.55mm，高30mm)
footprint 3006P (19.05mm*4.83mm*6.35mm(长*宽*高）)
pins: 1, 2, 3

## RPI40Pin
designator P?, comment 40Pin
footprint HDR-20X2 (Footprint not found)
pins: 1, 2, 3, 4, 5, 6, 7, 8, 9, 10, 11, 12, 13, 14, 15, 16, 17, 18, 19, 20, 21, 22, 23, 24, 25, 26, 27, 28, 29, 30, 31, 32, 33, 34, 35, 36, 37, 38, 39, 40

## RT9013
designator U?, comment RT9013-33GB
LDO 5.5V 500mA; BOM名称: 稳压芯片; 版权归属: 正点原子; Parameter: 芯片
footprint SOT23-5L (3x1.6x1.1mm(长宽高))
footprint SOT23-5N
footprint SOT23-5M (3x1.6x1.1mm(长宽高))
pins: 1 VIN, 2 GND, 3 EN, 4 NC, 5 OUT

## RT9013_1
designator U?, comment RT9013-18GB
LDO 5.5V 500mA; BOM名称: 稳压芯片; 版权归属: 正点原子; Parameter: 芯片
footprint SOT23-5L (3x1.6x1.1mm(长宽高))
footprint SOT23-5N
footprint SOT23-5M (3x1.6x1.1mm(长宽高))
pins: 1 VIN, 2 GND, 3 EN, 4 NC, 5 OUT

## RTL8211F-CG
designator U?, comment YT8531C/YT8531C-CA
footprint QFN40 (QFN, 40-Leads, Body 5.00x5.00mm, Pitch 0.40mm, Thermal Pad 3.70x3.70mm, IPC Low Density)
pins: 1 MDIP0 (io), 2 MDIN0 (io), 3 AVDD10 (power), 4 MDIP1 (io), 5 MDIN1 (io), 6 MDIP2 (io), 7 MDIN2 (io), 8 AVDD10 (power), 9 MDIP3 (io), 10 MDIN3 (io), 11 AVDD33 (power), 12 PHYRSTB (in), 13 MDC (in), 14 MDIO (io), 15 TXD3 (in), 16 TXD2 (in), 17 TXD1 (in), 18 TXD0 (in), 19 TXCTL (in), 20 TXCLK (in), 21 DVDD10 (power), 22 RXD3_PHYAD0 (out), 23 RXD2_PLLOFF (out), 24 RXD1_TXDLY (out), 25 RXD0_RXDLY (out), 26 RXCTL_PHYAD2, 27 RXCLK_PHYAD1, 28 DVDD_RG (power), 29 DVDD33 (power), 30 REG_OUT (out), 31 INT, 32 LED0_CFG_EXT (io), 33 LED1_CFG_LD0 (io), 34 LED2_CFG_LDO1 (out), 35 CLKOUT (out), 36 XTAL_IN (in), 37 XTAL_OUT_EXT_CLK (out), 38 AVDD10 (power), 39 RSET (out), 40 AVDD33 (power), 41 E-PAD (power)

## RTL8733BUUA
designator U?
footprint Model Name (Footprint not found)
footprint RTL8733BUBUA (RTL8733BUBUA WIFI&BT模组)
pins: 1 GND, 2 BT_RF, 3 WL_RF, 4 GND, 5 BT_PCM_IN, 6 BT_PCM_OUT, 7 BT_PCM_SYNC, 8 BT_PCM_CLK, 9 BT_WAKE_HOST, 10 HOST_WAKE_BT, 11 VDD33, 12 USB_DM, 13 USB_DP, 14 GND, 15 NC, 16 NC, 17 NC, 18 CHIP_EN, 19 HOST_WAKE_WL, 20 WL_WAKE_HOST

## SMA
designator BT ANT?
SMA-2.4G射频天线接口; 版权归属: 正点原子
footprint SMA-KWE (SMA 90度射频座)
pins: 1 ANT, 2 GND, 3 GND

## SMBJ
designator D?, comment SMBJ5.0A
TVS
footprint SMBJ (3.6*5.4)
pins: 1, 2

## SMBJ_1
designator D?, comment SMBJ3.3A
TVS
footprint SMBJ (3.6*5.4)
pins: 1, 2

## SMF05C
designator U?
footprint SOT363-6L (2.0x2.1x1.1mm(长宽高))
pins: 1 K1, 2 A, 3 K2, 4 K3, 5 K4, 6 K5

## SSW-1P
designator S?, comment SS-12D06
1路波动开关; BOM名称: 波动开关; 版权归属: 源创客
footprint SS-12F23
footprint SS-12D10
footprint MSK-12C01-07 (6.7*2.8*1.5mm(长宽高）)
footprint SS-12D06 (脚距3mm)
pins: 1, 2, 3

## TP
designator SPKR-?, comment TP_0.7  (value not drawn)
Test Point 0.7mm; Priority: A; RK PN: TESTPOINT_0R7
footprint TEST 1 (测试点1mm)
pins: 1

## USB3.0 A侧插
designator USB3.?, comment USB3.0 A侧插座
footprint USB3.0 A侧插
pins: 1 VBUS, 2 D-, 3 D+, 4 GND, 5 SSRX-, 6 SSRX+, 7 GND_DRAIN, 8 SSTX-, 9 SSTX+, S1 Shield, S2 Shield, S3 Shield, S4 Shield

## USB Type-C
designator UART?, comment USB TypeC
12P TypeC 母座; 版权归属: 正点原子; Parameter: 接口器件
footprint USB Type-C (USB Type-C 12P/16P)
footprint USB2.0-TYPE-C-16P (USB Type-C 12P/16P 加固定焊盘)
pins: 1 GND(A1+B12), 2 VBUS(A4+B9), 3 SBU2(B8), 4 CC1(A5), 5 D-2(B7), 6 D+1(A6), 7 D-1(A7), 8 D+2(B6), 9 SBU1(A8), 10 CC2(B5), 11 VBUS(B4+A9), 12 GND(B1+A12), SH1 Shield1, SH2 Shield2, SH3 Shield3, SH4 Shield4

## USB-A/S
designator USB_HOST?, comment USB
USB-A型母接口; 版权归属: 正点原子; Parameter: 接口器件
footprint USB-A/S_B (A型贴片母头，)
footprint USB-A/S_A (A型直插母头，)
footprint USB-A/S_C (A型贴片母头，)
footprint USB-A/S_D (A型直插母头，)
footprint USB-A/S_E (A型直插母头，)
footprint USB-A/S_F (A型侧插短体无卷边 90度母座)
footprint USB-A-AF10-SOP
pins: 1 VCC, 2 D-, 3 D+, 4 GND, 5 SHILED

## XC6206
designator U?, comment XC6206P332MR
LDO 5.5V 200-300mA; 版权归属: 正点原子; Parameter: 芯片
footprint SOT23-3L (3x1.3x1mm(长宽高))
footprint SOT23-3M (3x1.3x1mm(长宽高))
footprint SOT23-3N (3x1.3x1mm(长宽高))
pins: 1 GND, 2 Vout, 3 Vin

## XTAL-2P
designator X?, comment 32.768K
2脚无源晶振; BOM名称: 2脚晶振; 版权归属: 正点原子
footprint XTAL-3X10
footprint XTAL-3X8
footprint XTAL-2X6H
footprint XTAL-2X6
footprint XTAL-49S DIP
footprint XTAL-3215
footprint XTAL-3X8H
footprint XTAL-49S SMD
pins: 1, 2

## XTAL-4P
designator X?, comment 12M
4脚无源晶振; BOM名称: 4脚晶振; 版权归属: 源创客
footprint XTAL-5032
footprint XTAL-3225
footprint XTAL-7050 (7mm*5mm)
pins: 1 IN, 2 GND, 3 OUT, 4 GND

## XTAL-4P_1
designator X?, comment 25M
4脚无源晶振; BOM名称: 4脚晶振; 版权归属: 源创客
footprint XTAL-5032
footprint XTAL-3225
footprint XTAL-7050 (7mm*5mm)
pins: 1 IN, 2 GND, 3 OUT, 4 GND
